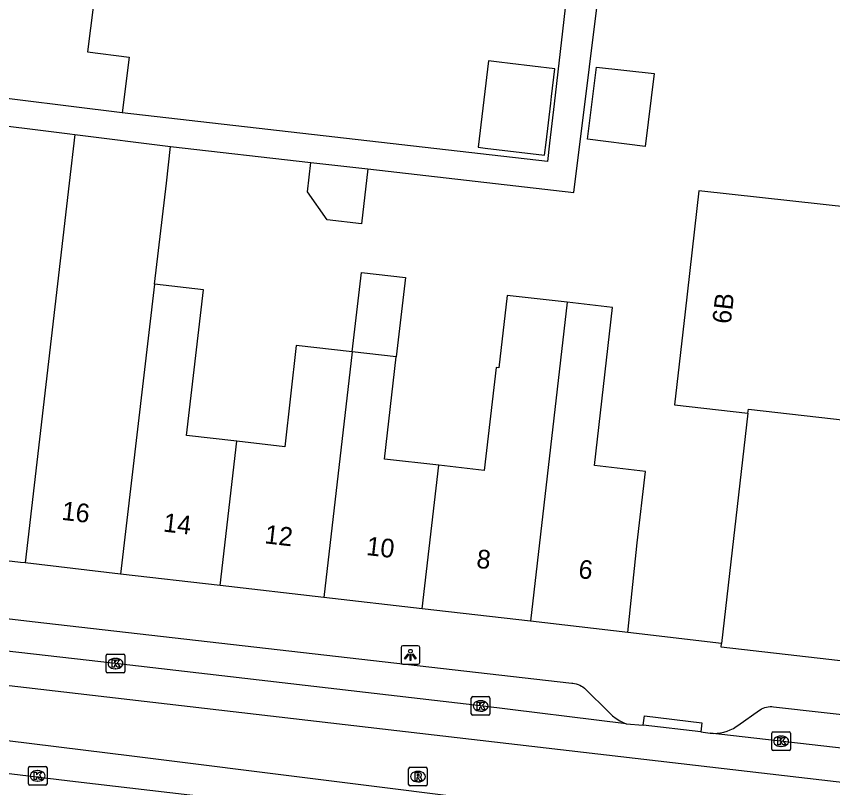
# Model space of a CAD drawing. Extents: x 161696 to 162377, y 380761 to 381673.
# Drawn here: x 162229.74 to 162273.45, y 381217.63 to 381258.94 of the extents above; entities that cross this region are included whole.
import ezdxf

# ---------------------------------------------------------------- set-up
doc = ezdxf.new("R2010")
doc.units = 0
for name, color, linetype in [('IMGEO_Kolk', 7, 'Continuous'), ('IMGEO_Lichtpunt', 7, 'Continuous'), ('IMGEO_Pand', 7, 'Continuous'), ('IMGEO_Pand_nummerreeks', 7, 'Continuous'), ('IMGEO_Rijbaan_lokaal_gesloten', 7, 'Continuous'), ('IMGEO_Rioolput', 7, 'Continuous'), ('IMGEO_Voetpad_open', 7, 'Continuous')]:
    doc.layers.add(name, color=color, linetype=linetype)

msp = doc.modelspace()

# ---------------------------------------------------------------- linework, layer by layer
at = {"layer": 'IMGEO_Kolk'}
for p, q in [((162234.624, 381224.778), (162235.476, 381224.778)), ((162234.549, 381223.852), (162234.549, 381224.704)), ((162235.037, 381224.558), (162235.062, 381224.558)), ((162235.55, 381224.704), (162235.55, 381223.852)), ((162235.06, 381223.998), (162235.035, 381223.998)), ((162235.476, 381223.778), (162234.624, 381223.778)), ((162254.1, 381221.582), (162254.1, 381222.434)), ((162254.175, 381222.508), (162255.027, 381222.508)), ((162254.588, 381222.288), (162254.613, 381222.288)), ((162255.101, 381222.434), (162255.101, 381221.582)), ((162254.611, 381221.728), (162254.586, 381221.728)), ((162255.027, 381221.508), (162254.175, 381221.508)), ((162270.192, 381219.692), (162270.192, 381220.544)), ((162270.267, 381220.618), (162271.119, 381220.618)), ((162271.193, 381220.544), (162271.193, 381219.692)), ((162270.68, 381220.398), (162270.705, 381220.398)), ((162271.119, 381219.618), (162270.267, 381219.618)), ((162270.703, 381219.838), (162270.678, 381219.838)), ((162230.383, 381217.839), (162230.383, 381218.691)), ((162230.458, 381218.765), (162231.31, 381218.765)), ((162231.384, 381218.691), (162231.384, 381217.839)), ((162230.871, 381218.545), (162230.896, 381218.545)), ((162230.894, 381217.985), (162230.869, 381217.985)), ((162231.31, 381217.765), (162230.458, 381217.765))]:
    msp.add_line(p, q, dxfattribs=at)
for points in [[(162234.624, 381224.778), (162235.476, 381224.778)], [(162234.549, 381223.852), (162234.549, 381224.704)], [(162234.87, 381224.478), (162234.993, 381224.478), (162234.993, 381224.327), (162235.123, 381224.478), (162235.287, 381224.478), (162235.141, 381224.327), (162235.294, 381224.078), (162235.142, 381224.078), (162235.057, 381224.242), (162234.993, 381224.175), (162234.993, 381224.078), (162234.87, 381224.078), (162234.87, 381224.478)], [(162235.55, 381224.704), (162235.55, 381223.852)], [(162235.476, 381223.778), (162234.624, 381223.778)], [(162254.1, 381221.582), (162254.1, 381222.434)], [(162254.175, 381222.508), (162255.027, 381222.508)], [(162254.421, 381222.208), (162254.544, 381222.208), (162254.544, 381222.057), (162254.674, 381222.208), (162254.838, 381222.208), (162254.692, 381222.057), (162254.845, 381221.808), (162254.693, 381221.808), (162254.608, 381221.972), (162254.544, 381221.905), (162254.544, 381221.808), (162254.421, 381221.808), (162254.421, 381222.208)], [(162255.101, 381222.434), (162255.101, 381221.582)], [(162255.027, 381221.508), (162254.175, 381221.508)], [(162270.192, 381219.692), (162270.192, 381220.544)], [(162270.267, 381220.618), (162271.119, 381220.618)], [(162271.193, 381220.544), (162271.193, 381219.692)], [(162270.513, 381220.318), (162270.636, 381220.318), (162270.636, 381220.167), (162270.766, 381220.318), (162270.93, 381220.318), (162270.784, 381220.167), (162270.937, 381219.918), (162270.785, 381219.918), (162270.7, 381220.082), (162270.636, 381220.015), (162270.636, 381219.918), (162270.513, 381219.918), (162270.513, 381220.318)], [(162271.119, 381219.618), (162270.267, 381219.618)], [(162230.383, 381217.839), (162230.383, 381218.691)], [(162230.458, 381218.765), (162231.31, 381218.765)], [(162231.384, 381218.691), (162231.384, 381217.839)], [(162230.704, 381218.465), (162230.827, 381218.465), (162230.827, 381218.314), (162230.957, 381218.465), (162231.121, 381218.465), (162230.975, 381218.314), (162231.128, 381218.065), (162230.976, 381218.065), (162230.891, 381218.229), (162230.827, 381218.162), (162230.827, 381218.065), (162230.704, 381218.065), (162230.704, 381218.465)], [(162231.31, 381217.765), (162230.458, 381217.765)]]:
    msp.add_lwpolyline(points, dxfattribs=at)
for centre, start, end in [((162234.626, 381224.702), 91.552, 178.448), ((162234.626, 381224.702), 91.552, 178.448), ((162235.474, 381224.702), 1.552, 88.448), ((162235.474, 381224.702), 1.552, 88.448), ((162234.626, 381223.854), 181.552, 268.448), ((162234.626, 381223.854), 181.552, 268.448), ((162235.474, 381223.854), 271.552, 358.448), ((162235.474, 381223.854), 271.552, 358.448), ((162254.177, 381222.432), 91.552, 178.448), ((162254.177, 381222.432), 91.552, 178.448), ((162255.025, 381222.432), 1.552, 88.448), ((162255.025, 381222.432), 1.552, 88.448), ((162254.177, 381221.584), 181.552, 268.448), ((162254.177, 381221.584), 181.552, 268.448), ((162255.025, 381221.584), 271.552, 358.448), ((162255.025, 381221.584), 271.552, 358.448), ((162270.269, 381220.542), 91.552, 178.448), ((162270.269, 381220.542), 91.552, 178.448), ((162271.117, 381220.542), 1.552, 88.448), ((162271.117, 381220.542), 1.552, 88.448), ((162270.269, 381219.694), 181.552, 268.448), ((162270.269, 381219.694), 181.552, 268.448), ((162271.117, 381219.694), 271.552, 358.448), ((162271.117, 381219.694), 271.552, 358.448), ((162230.46, 381218.689), 91.552, 178.448), ((162230.46, 381218.689), 91.552, 178.448), ((162231.308, 381218.689), 1.552, 88.448), ((162231.308, 381218.689), 1.552, 88.448), ((162230.46, 381217.841), 181.552, 268.448), ((162230.46, 381217.841), 181.552, 268.448), ((162231.308, 381217.841), 271.552, 358.448), ((162231.308, 381217.841), 271.552, 358.448)]:
    msp.add_arc(centre, 0.0765, start, end, dxfattribs=at)
for centre, major_axis, ratio, start_param, end_param in [((162235.036, 381224.278), (-0.387, 0.002), 0.722429, 4.712389, 7.853982), ((162235.061, 381224.278), (-0.39, 0.002), 0.717154, 1.570796, 4.712389), ((162254.587, 381222.008), (-0.387, 0.002), 0.722429, 4.712389, 7.853982), ((162254.612, 381222.008), (-0.39, 0.002), 0.717154, 1.570796, 4.712389), ((162270.679, 381220.118), (-0.387, 0.002), 0.722429, 4.712389, 7.853982), ((162270.704, 381220.118), (-0.39, 0.002), 0.717154, 1.570796, 4.712389), ((162230.87, 381218.265), (-0.387, 0.002), 0.722429, 4.712389, 7.853982), ((162230.895, 381218.265), (-0.39, 0.002), 0.717154, 1.570796, 4.712389)]:
    msp.add_ellipse(centre, major_axis=major_axis, ratio=ratio, start_param=start_param, end_param=end_param, dxfattribs=at)
at = {"layer": 'IMGEO_Lichtpunt'}
for p, q in [((162251.246, 381225.237), (162250.438, 381225.237)), ((162251.246, 381225.237), (162250.438, 381225.237)), ((162250.344, 381225.142), (162250.344, 381224.335)), ((162250.344, 381225.142), (162250.344, 381224.335)), ((162251.34, 381224.335), (162251.34, 381225.142)), ((162251.34, 381224.335), (162251.34, 381225.142)), ((162250.438, 381224.241), (162251.246, 381224.241)), ((162250.438, 381224.241), (162251.246, 381224.241))]:
    msp.add_line(p, q, dxfattribs=at)
for points in [[(162250.718, 381224.806), (162250.757, 381224.778), (162250.569, 381224.516), (162250.531, 381224.543), (162250.718, 381224.806)], [(162250.93, 381224.778), (162250.968, 381224.805), (162251.155, 381224.543), (162251.116, 381224.515), (162250.93, 381224.778)], [(162250.82, 381224.758), (162250.867, 381224.758), (162250.867, 381224.436), (162250.82, 381224.436), (162250.82, 381224.758)]]:
    msp.add_lwpolyline(points, dxfattribs=at)
msp.add_circle((162250.843, 381224.94), 0.0994, dxfattribs=at)
for centre, start, end in [((162250.438, 381225.142), 90, 180), ((162250.438, 381225.142), 90, 180), ((162251.246, 381225.142), 0, 90), ((162251.246, 381225.142), 0, 90), ((162250.438, 381224.335), 180, 270), ((162250.438, 381224.335), 180, 270), ((162251.246, 381224.335), 270, 0), ((162251.246, 381224.335), 270, 360)]:
    msp.add_arc(centre, 0.0946, start, end, dxfattribs=at)
at = {"layer": 'IMGEO_Pand'}
for points in [[(162230.666, 381259.968), (162233.874, 381259.569), (162233.559, 381257.039), (162235.776, 381256.763), (162235.405, 381253.776)], [(162254.471, 381251.926), (162254.84, 381251.882), (162258.022, 381251.504), (162258.102, 381252.178), (162258.352, 381254.284), (162258.395, 381254.641), (162258.572, 381256.138), (162256.181, 381256.421), (162255.586, 381256.492), (162255.021, 381256.559), (162254.471, 381251.926)], [(162263.412, 381251.974), (162260.316, 381252.36), (162260.796, 381256.217), (162263.897, 381255.872), (162263.412, 381251.974)], [(162235.405, 381253.776), (162227.061, 381254.815), (162222.099, 381255.433)], [(162221.768, 381253.998), (162226.873, 381253.362), (162227.279, 381253.312), (162232.613, 381252.648), (162232.864, 381252.617)], [(162232.864, 381252.617), (162232.563, 381250), (162230.216, 381229.665)], [(162232.864, 381252.617), (162238.004, 381251.977)], [(162237.14, 381244.598), (162237.773, 381250), (162238.004, 381251.977)], [(162248.568, 381250.77), (162248.23, 381247.824), (162246.383, 381248.036), (162245.322, 381249.539), (162245.503, 381251.12)], [(162245.503, 381251.12), (162248.568, 381250.77)], [(162281.057, 381247.971), (162266.291, 381249.587), (162265.551, 381243.111), (162264.983, 381238.143), (162268.913, 381237.694)], [(162247.726, 381240.971), (162248.215, 381245.221), (162250.571, 381244.951), (162250.084, 381240.701)], [(162237.14, 381244.598), (162235.323, 381229.075)], [(162241.538, 381236.182), (162238.859, 381236.489), (162239.754, 381244.298), (162237.14, 381244.598)], [(162259.229, 381243.627), (162256.021, 381243.995), (162255.576, 381240.111), (162255.43, 381240.128), (162254.799, 381234.621), (162252.362, 381234.9)], [(162259.229, 381243.627), (162257.263, 381226.541)], [(162262.479, 381225.938), (162262.981, 381230.74), (162263.42, 381234.568), (162260.691, 381234.881), (162261.662, 381243.348), (162259.229, 381243.627)], [(162247.726, 381240.971), (162244.732, 381241.314), (162244.11, 381235.887), (162241.538, 381236.182)], [(162247.726, 381240.971), (162246.212, 381227.817)], [(162250.084, 381240.701), (162247.726, 381240.971)], [(162252.362, 381234.9), (162249.457, 381235.233), (162250.084, 381240.701)], [(162268.913, 381237.694), (162268.938, 381237.91), (162293.569, 381235.098)], [(162268.913, 381237.694), (162267.502, 381225.358)], [(162240.652, 381228.46), (162241.538, 381236.182)], [(162251.476, 381227.209), (162252.362, 381234.9)], [(162230.216, 381229.665), (162229.966, 381229.694), (162224.64, 381230.309), (162218.981, 381230.963)], [(162235.323, 381229.075), (162230.216, 381229.665)], [(162240.652, 381228.46), (162235.323, 381229.075)], [(162246.212, 381227.817), (162240.652, 381228.46)], [(162251.476, 381227.209), (162246.212, 381227.817)], [(162257.263, 381226.541), (162251.476, 381227.209)], [(162262.479, 381225.938), (162257.263, 381226.541)], [(162291.159, 381222.448), (162267.479, 381225.155), (162267.502, 381225.358)]]:
    msp.add_lwpolyline(points, dxfattribs=at)
at = {"layer": 'IMGEO_Rijbaan_lokaal_gesloten'}
for points in [[(162181.003, 381226.106), (162206.021, 381223.02), (162219.985, 381221.297), (162235.933, 381219.33), (162285.948, 381213.063)], [(162286.396, 381216.457), (162220.264, 381224.141), (162220.506, 381225.942)], [(162262.395, 381221.059), (162254.6, 381222.007), (162235.045, 381224.277), (162221.075, 381225.863)], [(162262.395, 381221.059), (162263.309, 381220.982)], [(162266.386, 381220.615), (162263.309, 381220.982)], [(162266.386, 381220.615), (162266.894, 381220.55)], [(162278.711, 381219.208), (162278.27, 381219.254), (162266.894, 381220.55)], [(162220.144, 381219.504), (162232.915, 381217.962), (162246.988, 381216.323)]]:
    msp.add_lwpolyline(points, dxfattribs=at)
at = {"layer": 'IMGEO_Rioolput'}
for p, q in [((162250.82, 381218.724), (162251.672, 381218.724)), ((162250.745, 381217.798), (162250.745, 381218.65)), ((162251.233, 381218.504), (162251.258, 381218.504)), ((162251.746, 381218.65), (162251.746, 381217.798)), ((162251.256, 381217.944), (162251.231, 381217.944)), ((162251.672, 381217.724), (162250.82, 381217.724))]:
    msp.add_line(p, q, dxfattribs=at)
for points in [[(162250.82, 381218.724), (162251.672, 381218.724)], [(162250.745, 381217.798), (162250.745, 381218.65)], [(162251.334, 381218.422), (162251.082, 381218.424), (162251.082, 381218.024)], [(162251.26, 381218.343), (162251.206, 381218.343), (162251.206, 381218.262)], [(162251.206, 381218.262), (162251.258, 381218.262)], [(162251.746, 381218.65), (162251.746, 381217.798)], [(162251.082, 381218.024), (162251.206, 381218.024), (162251.206, 381218.186), (162251.217, 381218.186)], [(162251.264, 381218.157), (162251.335, 381218.024), (162251.475, 381218.024), (162251.41, 381218.15)], [(162251.672, 381217.724), (162250.82, 381217.724)]]:
    msp.add_lwpolyline(points, dxfattribs=at)
for centre, radius, start, end in [((162250.822, 381218.648), 0.0765, 91.552, 178.448), ((162250.822, 381218.648), 0.0765, 91.552, 178.448), ((162251.67, 381218.648), 0.0765, 1.552, 88.448), ((162251.67, 381218.648), 0.0765, 1.552, 88.448), ((162251.242, 381218.451), 0.19, 274.7715, 282.9687), ((162251.266, 381218.247), 0.0964, 77.0061, 93.1865), ((162251.28, 381218.304), 0.0378, 276.6634, 79.6772), ((162251.333, 381218.312), 0.109, 350.3612, 89.416), ((162251.331, 381218.312), 0.112, 277.5842, 350.9817), ((162250.822, 381217.8), 0.0765, 181.552, 268.448), ((162250.822, 381217.8), 0.0765, 181.552, 268.448), ((162251.216, 381218.133), 0.0533, 26.0293, 88.6989), ((162251.315, 381218.097), 0.108, 29.5134, 73.7905), ((162251.67, 381217.8), 0.0765, 271.552, 358.448), ((162251.67, 381217.8), 0.0765, 271.552, 358.448)]:
    msp.add_arc(centre, radius, start, end, dxfattribs=at)
for centre, major_axis, ratio, start_param, end_param in [((162251.232, 381218.224), (-0.387, 0.002), 0.722429, 4.712389, 7.853982), ((162251.257, 381218.224), (-0.39, 0.002), 0.717154, 1.570796, 4.712389)]:
    msp.add_ellipse(centre, major_axis=major_axis, ratio=ratio, start_param=start_param, end_param=end_param, dxfattribs=at)
at = {"layer": 'IMGEO_Voetpad_open'}
for points in [[(162248.568, 381250.77), (162259.583, 381249.511), (162263.772, 381283.024), (162265.259, 381294.924), (162266.831, 381307.5), (162271.787, 381347.044)], [(162261.045, 381278.03), (162261.283, 381278), (162261.27, 381277.887), (162260.634, 381272.474), (162260.014, 381267.198), (162258.536, 381254.262), (162258.295, 381252.155), (162258.183, 381251.173), (162235.405, 381253.776)], [(162238.004, 381251.977), (162245.503, 381251.12)], [(162224.538, 381227.245), (162230.584, 381226.531), (162259.491, 381223.226), (162259.529, 381223.224), (162259.627, 381223.211), (162259.724, 381223.19), (162259.818, 381223.161), (162259.909, 381223.123), (162259.996, 381223.077), (162260.079, 381223.024), (162260.157, 381222.963), (162261.495, 381221.641), (162261.67, 381221.483), (162261.859, 381221.341), (162262.06, 381221.217), (162262.271, 381221.111), (162262.395, 381221.059)], [(162267.502, 381225.358), (162262.479, 381225.938)], [(162266.894, 381220.55), (162267.077, 381220.538), (162267.261, 381220.543), (162267.443, 381220.563), (162267.623, 381220.601), (162267.799, 381220.654), (162267.969, 381220.722), (162268.133, 381220.806), (162268.289, 381220.903), (162268.378, 381220.969), (162269.528, 381221.778), (162269.565, 381221.804), (162269.647, 381221.852), (162269.732, 381221.893), (162269.821, 381221.926), (162269.912, 381221.951), (162270.005, 381221.968), (162270.099, 381221.976), (162270.194, 381221.976), (162270.288, 381221.968), (162275.867, 381221.329)], [(162263.309, 381220.982), (162263.368, 381221.478), (162266.445, 381221.111), (162266.386, 381220.615)]]:
    msp.add_lwpolyline(points, dxfattribs=at)

# ---------------------------------------------------------------- texts
at = {"layer": 'IMGEO_Pand_nummerreeks'}
for s, rotation, p in [('6B', 83.48, (162267.99, 381242.439)), ('16', 353.4103, (162232.133, 381231.981)), ('14', 353.4103, (162237.57, 381231.352)), ('12', 353.4103, (162243.004, 381230.724)), ('10', 353.4103, (162248.448, 381230.096)), ('8', 353.4103, (162254.342, 381229.414)), ('6', 353.0048, (162259.799, 381228.866))]:
    msp.add_text(s, height=1, rotation=rotation, dxfattribs=at).set_placement(p)

doc.saveas('drawing.dxf')
